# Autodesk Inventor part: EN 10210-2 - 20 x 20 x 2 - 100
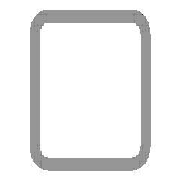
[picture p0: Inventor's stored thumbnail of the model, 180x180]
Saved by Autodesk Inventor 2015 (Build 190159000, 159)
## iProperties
Created: 2015-05
Part Number: EN 10210-2 - 20 x 20 x 2 - 100
Material: Steel, Mild
Description: Tube
Document SubType Name: Modeling
Standard: DIN
Designer: TREINA6
Standard Revision: 1997
Standards Organization: DIN
Language: en-US
Size Designation: 20 x 20 x 2
Categories: <MemberInstance><Categories><Category DisplayName="Structural Shapes" InternalName="089c4875-fa83-4c05-b084-43b9cc11f5ed" Mnemonic="GRDR"><CategoryParameter Dis
Stock Number: 20 x 20 x 2
Density: 7.85 g/cm^3
Appearance: Semi-Polished
_CCFamilyMember: 1
_CCFamilyDisplayName: DIN EN 10210-2 (Square) - Tube
_FrameMemberDoc: Frame Member File
_Version: 15.0.0
_GetPNFromCC: 1
IsCustomPart: 1
Author: TREINA6
G_L: 100,000 mm
G_W: 20,000 mm
G_H: 20,000 mm
+AC749DCF-2404-4771-B15D-8F815B6C9E4F+CUTDETAIL1: Miter 45,00 deg
+0C994340-A7AD-46E7-A811-0656540D89CB+CUTDETAIL2: Miter 45,00 deg
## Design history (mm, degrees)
node "Start plane"
node "End plane"
sketch "Sketch"
  geometry: L1 (-10, -7)-(-10, 7); L2 (-7, 10)-(7, 10); L3 (10, 7)-(10, -7); L4 (7, -10)-(-7, -10); L5 (-7, 8)-(7, 8); L6 (8, 7)-(8, -7); L7 (7, -8)-(-7, -8); L8 (-8, -7)-(-8, 7); L9 (0, 14.87)-(0, -14.87) reference; L10 (-14.87, 0)-(14.87, 0) reference; A1 r 3 centre (-7, -7) between (-10, -7) and (-7, -10); A2 r 3 centre (-7, 7) between (-7, 10) and (-10, 7); A3 r 3 centre (7, 7) between (10, 7) and (7, 10); A4 r 3 centre (7, -7) between (7, -10) and (10, -7); A5 r 1 centre (-7, 7) between (-7, 8) and (-8, 7); A6 r 1 centre (7, 7) between (8, 7) and (7, 8); A7 r 1 centre (7, -7) between (7, -8) and (8, -7); A8 r 1 centre (-7, -7) between (-8, -7) and (-7, -8)
  constraints: 16 end point, 16 point on circle, 8 centre point, 8 tangent, 4 parallel, 3 equal radius, 2 perpendicular, 7 other
  dimensions: "d7" = 3 radius of A1 (= G_IR); "d10" = 20 distance between parallel lines of L2 L4 (= G_H); "d11" = 20 distance between parallel lines of L1 L3 (= G_W); "d12" = 2 distance between parallel lines of L3 L6 (= G_T); "d15" = 10 distance between parallel lines of L2 L10 (= 0.5 x d10); "d16" = 10 distance between parallel lines of L9 L3 (= 0.5 x d11)
extrude "Body" new body sketch "Sketch" stored distance "d3" = 100 (= G_L); taper "d4" = 0 deg
node "Driven Length"
  sketch "Sketch3"
    geometry: L1 (0, 0)-(10, 0) reference
    constraints: 2 end point, 1 horizontal
  workplane "Work Plane3"
  sketch "Sketch4"
    geometry: L1 (-2, 0)-(12, 0) reference; L2 (-2, 100)-(12, 100) reference
    dimensions: "d18" = 100 distance between parallel lines of L1 L2 (derived)
workplane "Work Plane4"
split "Split1"
workplane "Work Plane5"
split "Split2"
body "Solid1"
other parameters: "G_W" = 20 [user parameter; used in 1 equation term], "G_H" = 20 [user parameter; used in 1 equation term], "G_T" = 2 [user parameter; used in 1 equation term], "G_IR" = 3 [user parameter; used in 1 equation term], "G_L" = 100 (= d18) [user parameter; used in 1 equation term], "G_OFFSET_START" = 0 [user parameter; used in 1 equation term], "G_OFFSET_END" = 0 [user parameter; used in 1 equation term], "d13" = 0 (computed from G_OFFSET_START), "d17" = 90 deg
